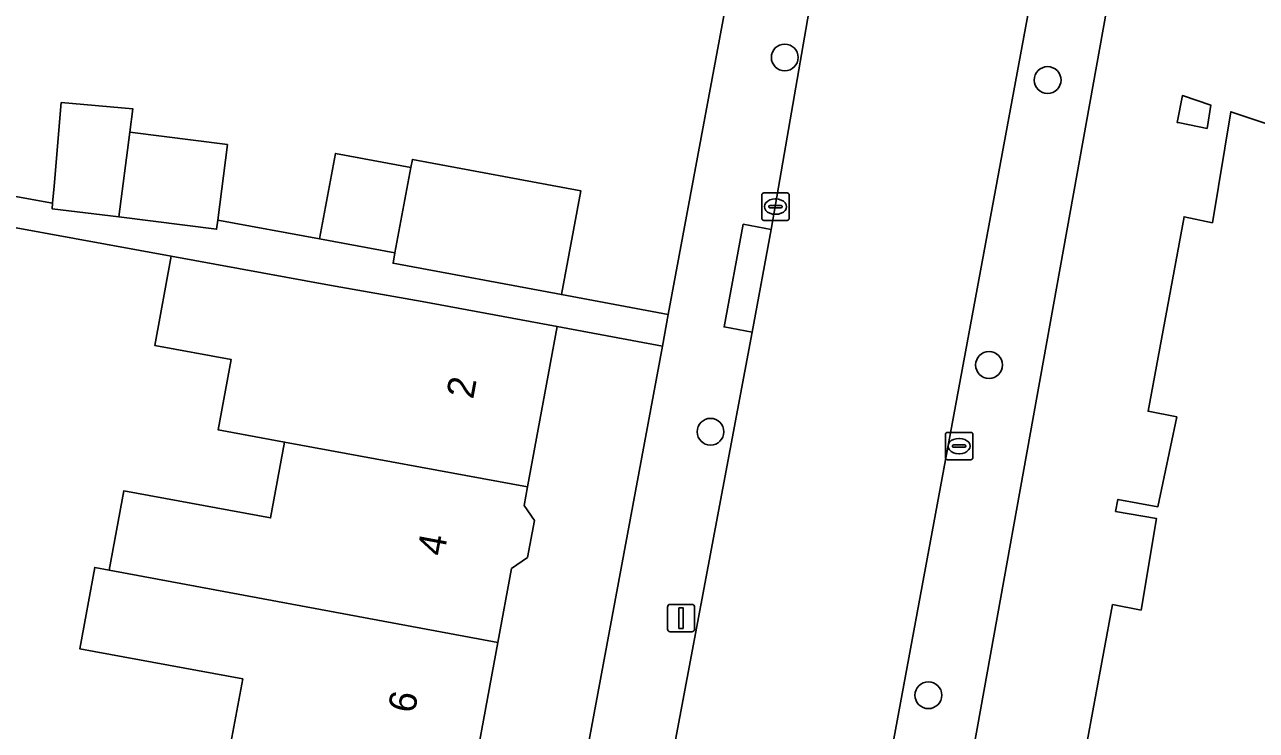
# Model space of a CAD drawing. Extents: x 158086 to 159499, y 382904 to 383981.
# Drawn here: x 158552.78 to 158597.73, y 383325.41 to 383351.15 of the extents above; entities that cross this region are included whole.
import ezdxf

# ---------------------------------------------------------------- set-up
doc = ezdxf.new("R2010")
doc.units = 0
for name, color, linetype in [('IMGEO_Boom', 7, 'Continuous'), ('IMGEO_Erf', 7, 'Continuous'), ('IMGEO_Kolk', 7, 'Continuous'), ('IMGEO_Lichtmast', 7, 'Continuous'), ('IMGEO_Pand', 7, 'Continuous'), ('IMGEO_Pand_nummerreeks', 7, 'Continuous'), ('IMGEO_Rijbaan_lokaal_open', 7, 'Continuous'), ('IMGEO_Voetpad_open', 7, 'Continuous')]:
    doc.layers.add(name, color=color, linetype=linetype)

msp = doc.modelspace()

# ---------------------------------------------------------------- linework, layer by layer
at = {"layer": 'IMGEO_Boom'}
for centre in [(158580.52, 383349.955), (158590.11, 383349.131), (158587.972, 383338.737), (158577.81, 383336.3), (158585.759, 383326.691)]:
    msp.add_circle(centre, 0.489, dxfattribs=at)
at = {"layer": 'IMGEO_Erf'}
for points in [[(158545.19, 383346.196), (158553.805, 383344.646), (158553.858, 383345.263), (158554.12, 383348.309), (158556.729, 383348.085), (158556.62, 383347.235), (158560.183, 383346.777), (158559.829, 383344.025), (158563.548, 383343.339), (158564.127, 383346.453), (158566.876, 383345.941), (158566.931, 383346.236), (158573.075, 383345.091), (158572.369, 383341.303), (158576.268, 383340.577), (158580.776, 383364.79)], [(158688.925, 383329.143), (158595.466, 383360.699), (158593.935, 383359.866), (158593.193, 383356.252), (158592.385, 383352.344), (158585.243, 383312.721), (158584.576, 383309.191), (158573.515, 383250), (158565.366, 383205.337)], [(158597.83, 383310.49), (158594.095, 383311.168), (158589.175, 383312.06), (158589.874, 383315.836), (158589.975, 383315.818), (158590.916, 383315.65), (158591.45, 383319.003), (158589.993, 383319.25), (158590.075, 383319.679), (158591.532, 383319.397), (158592.192, 383322.707), (158591.168, 383322.9), (158592.481, 383329.996), (158593.521, 383329.798), (158594.085, 383333.132), (158592.591, 383333.398), (158592.674, 383333.836), (158594.137, 383333.568), (158594.823, 383336.845), (158593.778, 383337.052), (158595.09, 383344.142), (158596.125, 383343.926), (158596.791, 383347.973), (158599.482, 383347.068)], [(158560.238, 383324.561), (158560.74, 383327.288), (158555.322, 383328.286), (158554.794, 383328.384), (158555.341, 383331.35), (158555.868, 383331.251), (158556.402, 383334.144), (158561.759, 383333.157), (158562.269, 383335.923), (158559.85, 383336.369), (158560.323, 383338.936), (158557.533, 383339.45), (158558.133, 383342.705), (158548.665, 383344.43), (158547.943, 383344.561), (158547.615, 383341.582), (158550.929, 383340.972), (158550.385, 383338.02), (158551.913, 383337.738), (158550.819, 383331.809), (158546.222, 383332.656), (158543.186, 383333.215), (158541.994, 383321.755)], [(158564.087, 383275.159), (158576.054, 383339.428), (158572.209, 383340.144), (158571.13, 383334.287), (158571.005, 383333.61), (158571.384, 383333.06), (158571.136, 383331.716), (158570.549, 383331.311), (158570.051, 383328.609), (158569.007, 383322.944)]]:
    msp.add_lwpolyline(points, dxfattribs=at)
msp.add_lwpolyline([(158595.93, 383347.368), (158594.938, 383347.567), (158594.831, 383347.588), (158595.027, 383348.566), (158596.07, 383348.215)], close=True, dxfattribs=at)
at = {"layer": 'IMGEO_Kolk'}
for p, q in [((158579.681, 383344.087), (158579.681, 383344.939)), ((158579.756, 383345.013), (158580.608, 383345.013)), ((158580.169, 383344.793), (158580.194, 383344.793)), ((158580.682, 383344.939), (158580.682, 383344.087)), ((158579.94, 383344.507), (158579.94, 383344.519)), ((158580.378, 383344.47), (158579.98, 383344.47)), ((158579.983, 383344.556), (158580.381, 383344.556)), ((158580.192, 383344.233), (158580.167, 383344.233)), ((158580.424, 383344.519), (158580.424, 383344.507)), ((158580.608, 383344.013), (158579.756, 383344.013)), ((158586.38, 383335.352), (158586.38, 383336.204)), ((158586.455, 383336.278), (158587.307, 383336.278)), ((158586.868, 383336.058), (158586.893, 383336.058)), ((158587.381, 383336.204), (158587.381, 383335.352)), ((158586.639, 383335.772), (158586.639, 383335.784)), ((158587.077, 383335.735), (158586.679, 383335.735)), ((158586.682, 383335.821), (158587.08, 383335.821)), ((158587.123, 383335.784), (158587.123, 383335.772)), ((158587.307, 383335.278), (158586.455, 383335.278)), ((158586.891, 383335.498), (158586.866, 383335.498))]:
    msp.add_line(p, q, dxfattribs=at)
for points in [[(158579.681, 383344.087), (158579.681, 383344.939)], [(158579.756, 383345.013), (158580.608, 383345.013)], [(158580.682, 383344.939), (158580.682, 383344.087)], [(158580.608, 383344.013), (158579.756, 383344.013)], [(158586.38, 383335.352), (158586.38, 383336.204)], [(158586.455, 383336.278), (158587.307, 383336.278)], [(158587.381, 383336.204), (158587.381, 383335.352)], [(158587.307, 383335.278), (158586.455, 383335.278)]]:
    msp.add_lwpolyline(points, dxfattribs=at)
for centre, radius, start, end in [((158579.758, 383344.937), 0.0765, 91.552, 178.448), ((158579.758, 383344.937), 0.0765, 91.552, 178.448), ((158580.606, 383344.937), 0.0765, 1.552, 88.448), ((158580.606, 383344.937), 0.0765, 1.552, 88.448), ((158579.98, 383344.516), 0.0403, 85.8775, 175.7526), ((158579.977, 383344.506), 0.0366, 178.938, 274.7102), ((158580.381, 383344.513), 0.043, 264.8664, 352.4533), ((158580.385, 383344.518), 0.0386, 1.7309, 96.639), ((158579.758, 383344.089), 0.0765, 181.552, 268.448), ((158579.758, 383344.089), 0.0765, 181.552, 268.448), ((158580.606, 383344.089), 0.0765, 271.552, 358.448), ((158580.606, 383344.089), 0.0765, 271.552, 358.448), ((158586.457, 383336.202), 0.0765, 91.552, 178.448), ((158586.457, 383336.202), 0.0765, 91.552, 178.448), ((158587.305, 383336.202), 0.0765, 1.552, 88.448), ((158587.305, 383336.202), 0.0765, 1.552, 88.448), ((158586.679, 383335.781), 0.0403, 85.8775, 175.7526), ((158586.676, 383335.771), 0.0366, 178.938, 274.7102), ((158587.08, 383335.778), 0.043, 264.8664, 352.4533), ((158587.084, 383335.783), 0.0386, 1.7309, 96.639), ((158586.457, 383335.354), 0.0765, 181.552, 268.448), ((158586.457, 383335.354), 0.0765, 181.552, 268.448), ((158587.305, 383335.354), 0.0765, 271.552, 358.448), ((158587.305, 383335.354), 0.0765, 271.552, 358.448)]:
    msp.add_arc(centre, radius, start, end, dxfattribs=at)
for centre, major_axis, ratio, start_param, end_param in [((158580.168, 383344.513), (-0.387, 0.002), 0.722429, 4.712389, 7.853982), ((158580.193, 383344.513), (-0.39, 0.002), 0.717154, 1.570796, 4.712389), ((158586.867, 383335.778), (-0.387, 0.002), 0.722429, 4.712389, 7.853982), ((158586.892, 383335.778), (-0.39, 0.002), 0.717154, 1.570796, 4.712389)]:
    msp.add_ellipse(centre, major_axis=major_axis, ratio=ratio, start_param=start_param, end_param=end_param, dxfattribs=at)
at = {"layer": 'IMGEO_Lichtmast'}
for p, q in [((158576.239, 383329.105), (158576.239, 383329.905)), ((158576.239, 383329.905), (158576.239, 383329.105)), ((158576.339, 383330.005), (158577.129, 383330.005)), ((158577.129, 383330.005), (158576.339, 383330.005)), ((158577.229, 383329.905), (158577.229, 383329.105)), ((158577.229, 383329.105), (158577.229, 383329.905)), ((158577.129, 383329.005), (158576.339, 383329.005)), ((158576.339, 383329.005), (158577.129, 383329.005))]:
    msp.add_line(p, q, dxfattribs=at)
msp.add_lwpolyline([(158576.659, 383329.88), (158576.809, 383329.88), (158576.809, 383329.13), (158576.659, 383329.13), (158576.659, 383329.88)], dxfattribs=at)
for centre, start, end in [((158576.339, 383329.905), 90, 180), ((158576.339, 383329.905), 90, 180), ((158577.129, 383329.905), 0, 90), ((158577.129, 383329.905), 360, 90), ((158576.339, 383329.105), 180, 270), ((158576.339, 383329.105), 180, 270), ((158577.129, 383329.105), 270, 0), ((158577.129, 383329.105), 270, 0)]:
    msp.add_arc(centre, 0.1, start, end, dxfattribs=at)
at = {"layer": 'IMGEO_Pand'}
for points in [[(158556.62, 383347.235), (158556.729, 383348.085), (158554.12, 383348.309), (158553.858, 383345.263), (158553.805, 383344.646), (158553.787, 383344.435), (158556.223, 383344.144)], [(158596.07, 383348.215), (158595.027, 383348.566), (158594.831, 383347.588), (158594.938, 383347.567), (158595.93, 383347.368)], [(158556.62, 383347.235), (158556.223, 383344.144), (158559.786, 383343.686), (158559.829, 383344.025), (158560.183, 383346.777)], [(158566.876, 383345.941), (158564.127, 383346.453), (158563.548, 383343.339), (158566.296, 383342.828)], [(158573.075, 383345.091), (158566.931, 383346.236), (158566.876, 383345.941), (158566.296, 383342.828), (158566.225, 383342.447), (158572.369, 383341.303)], [(158571.13, 383334.287), (158572.209, 383340.144), (158567.292, 383341.05), (158563.903, 383341.654), (158558.133, 383342.705), (158557.533, 383339.45), (158560.323, 383338.936), (158559.85, 383336.369), (158562.269, 383335.923)], [(158555.868, 383331.251), (158570.051, 383328.609), (158570.549, 383331.311), (158571.136, 383331.716), (158571.384, 383333.06), (158571.005, 383333.61), (158571.13, 383334.287), (158562.269, 383335.923), (158561.759, 383333.157), (158556.402, 383334.144)], [(158570.051, 383328.609), (158555.868, 383331.251), (158555.341, 383331.35), (158554.794, 383328.384), (158555.322, 383328.286), (158560.74, 383327.288), (158560.238, 383324.561), (158564.09, 383323.85), (158569.007, 383322.944)]]:
    msp.add_lwpolyline(points, close=True, dxfattribs=at)
msp.add_lwpolyline([(158599.482, 383347.068), (158596.791, 383347.973), (158596.125, 383343.926), (158595.09, 383344.142), (158593.778, 383337.052), (158594.823, 383336.845), (158594.137, 383333.568), (158592.674, 383333.836), (158592.591, 383333.398), (158594.085, 383333.132), (158593.521, 383329.798), (158592.481, 383329.996), (158591.168, 383322.9), (158592.192, 383322.707), (158591.532, 383319.397), (158590.075, 383319.679), (158589.993, 383319.25), (158591.45, 383319.003), (158590.916, 383315.65), (158589.975, 383315.818), (158589.874, 383315.836), (158589.175, 383312.06), (158594.095, 383311.168), (158597.83, 383310.49)], dxfattribs=at)
at = {"layer": 'IMGEO_Rijbaan_lokaal_open'}
msp.add_lwpolyline([(158581.664, 383309.815), (158582.307, 383313.283), (158590.03, 383354.993), (158591.055, 383360.592), (158583.271, 383362.073), (158582.458, 383357.725), (158580.025, 383343.68), (158579.328, 383339.933), (158566.865, 383273.653), (158566.207, 383270.094), (158565.773, 383267.781), (158562.609, 383250.486), (158565.402, 383250), (158570.464, 383249.119), (158570.635, 383250), (158579.736, 383299.401)], close=True, dxfattribs=at)
at = {"layer": 'IMGEO_Voetpad_open'}
for points in [[(158583.632, 383364.455), (158580.776, 383364.79), (158576.268, 383340.577), (158576.054, 383339.428), (158564.087, 383275.159), (158563.934, 383274.338), (158560.424, 383255.241), (158559.351, 383249.35), (158558.62, 383245.875)], [(158562.417, 383249.462), (158562.518, 383250), (158562.609, 383250.486), (158565.773, 383267.781), (158566.207, 383270.094), (158565.184, 383270.283), (158565.842, 383273.842), (158566.865, 383273.653), (158579.328, 383339.933), (158578.306, 383340.123), (158579.003, 383343.87), (158580.025, 383343.68), (158582.458, 383357.725)], [(158548.665, 383344.43), (158558.133, 383342.705), (158563.903, 383341.654), (158567.292, 383341.05), (158572.209, 383340.144), (158576.054, 383339.428), (158576.268, 383340.577), (158572.369, 383341.303), (158566.225, 383342.447), (158566.296, 383342.828), (158563.548, 383343.339), (158559.829, 383344.025), (158559.786, 383343.686), (158556.223, 383344.144), (158553.787, 383344.435), (158553.805, 383344.646), (158545.19, 383346.196)]]:
    msp.add_lwpolyline(points, dxfattribs=at)
for points in [[(158592.385, 383352.344), (158593.193, 383356.252), (158593.935, 383359.866), (158591.055, 383360.592), (158590.03, 383354.993), (158582.307, 383313.283), (158585.243, 383312.721)], [(158579.328, 383339.933), (158580.025, 383343.68), (158579.003, 383343.87), (158578.306, 383340.123)]]:
    msp.add_lwpolyline(points, close=True, dxfattribs=at)

# ---------------------------------------------------------------- texts
at = {"layer": 'IMGEO_Pand_nummerreeks'}
for s, rotation, p in [('2', 79.4544, (158569.147, 383337.466)), ('4', 79.4521, (158568.08, 383331.735)), ('6', 79.4521, (158567.013, 383326.001))]:
    msp.add_text(s, height=1, rotation=rotation, dxfattribs=at).set_placement(p)

doc.saveas('drawing.dxf')
